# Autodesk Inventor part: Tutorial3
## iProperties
Shininess: 64.0
Length Units: 11269
Angle Units: 11279
Time Units: 11290
Mass Units: 11283
Length Display Precision: 3
Angle Display Precision: 2
Compacted: True
Part Number: Tutorial3
Document SubType Name: Modeling
Created: 2003-10
Designer: Owner
Manufacturer: Standard
Standards Organization: Custom
Density: 0.0
Volumn: 0.0
Area: 0.0
PropertySet Name: Model Information
Control State: 0
Master: False
Checked Out: False
Author: Owner
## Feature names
1. Extrusion1
